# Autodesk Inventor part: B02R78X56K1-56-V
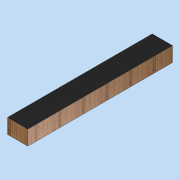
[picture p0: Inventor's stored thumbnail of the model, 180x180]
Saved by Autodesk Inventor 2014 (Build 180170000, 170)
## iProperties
Created: 2011-08
Part Number: B02R78X56K1-56-V
Document SubType Name: Modeling
Designer: david.appleford
Density: 0.413245 g/cm^3
Description: Roof Edge Beam 0.5w - 1 Lock
Mass: 1000 g
Surface Area: 1572.08 cm^2
Volume: 2419.87 cm^3
Cost Center: £10.00
Material: 000 Redwood
Appearance: Wood (Oak)
Justset: False
Title: Roof Edge Beam 0.5w - 1 Lock
Author: david.appleford
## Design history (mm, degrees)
sketch "Sketch1"
  geometry: L1 (39, -34)-(-39, -34); L2 (-39, -34)-(-39, 520); L3 (-39, 520)-(39, 520); L4 (39, 520)-(39, -34); 1 further point
  constraints: 8 end point, 2 parallel, 1 horizontal, 1 perpendicular, 1 other
  dimensions: "d2" = 78 distance between parallel lines of L2 L4; "d3" = 34 distance from line of point (0, 0) L1; "d4" = 39 distance from line of point (0, 0) L2 (= 0.5 x d2); "d5" = 554 distance of L3.end L1.start
extrude "Extrusion1" new body sketch "Sketch1" distance "d0" = 56; taper "d1" = 0 deg
body "Solid1"
